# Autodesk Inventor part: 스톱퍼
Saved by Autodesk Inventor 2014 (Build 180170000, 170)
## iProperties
Created: 2025-06
Part Number: 스톱퍼
Material: 강철, 연강
Document SubType Name: Modeling
Designer: dg
Density: 7.86 g/cm^3
Appearance: 강철
Mass: 62.4467 g
Surface Area: 35.6119 cm^2
Volume: 7.94487 cm^3
Author: jhkim
Creation Date: 2025-05-27
Sending System: Autodesk Inventor 2026
Preprocessor: ST-DEVELOPER v20.1
Author: dg
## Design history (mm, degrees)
node "스톱퍼1"
node "솔리드1"
node "기준1"
